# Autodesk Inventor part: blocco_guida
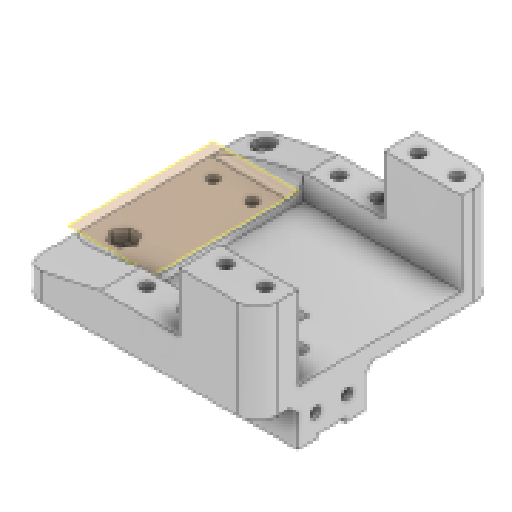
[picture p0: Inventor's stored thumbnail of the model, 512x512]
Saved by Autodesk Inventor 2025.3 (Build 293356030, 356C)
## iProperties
Created: 2026-02
Part Number: blocco_guida
Material: Plastica PET
Document SubType Name: Modeling
Designer: R5800u
Density: 1.541 g/cm^3
Appearance: Alluminio - Scuro
Author: R5800u
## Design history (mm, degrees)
sketch "Schizzo1"
  geometry: L1 (30, -3.5)-(-30, -3.5); L2 (-30, -3.5)-(-30, 3.5); L3 (-30, 3.5)-(30, 3.5); L4 (30, 3.5)-(30, -3.5); L5 (30, -3.5)-(-30, 3.5); L6 (-30, -3.5)-(30, 3.5); L7 (30, -3.5)-(-30, -3.5); L8 (-30, -3.5)-(-30, -8.5); L9 (-30, -8.5)-(30, -8.5); L10 (30, -8.5)-(30, -3.5); L11 (30, 3.5)-(-30, 3.5); L12 (-30, 3.5)-(-30, 8.5); L13 (-30, 8.5)-(30, 8.5); L14 (30, 8.5)-(30, 3.5); 3 further points
  constraints: 28 end point, 6 parallel, 3 horizontal, 3 perpendicular, 2 midpoint, 1 point on line
  dimensions: "d0" = 60 distance of L2.end L3.end; "d1" = 7 distance of L1.end L2.end; "d2" = 5 distance of L8.end L7.end; "d3" = 5 distance of L11.end L12.end
node "Piano di lavoro1"
extrude "Estrusione1" new body sketch "Schizzo1" stored distance "d4" = 10; taper "d5" = 0 deg
extrude "Estrusione2" cut sketch "Schizzo1" distance "d6" = 1; taper "d7" = 0 deg
sketch "Schizzo2"
  geometry: L1 (-30, 8.5)-(30, 8.5) reference; L2 (-16, -8.5)-(16, -8.5); L3 (16, -8.5)-(16, 8.5); L4 (16, 8.5)-(-16, 8.5); L5 (-16, 8.5)-(-16, -8.5); L6 (-16, -8.5)-(16, 8.5); L7 (16, -8.5)-(-16, 8.5); 2 further points
  constraints: 12 end point, 2 midpoint, 2 parallel, 1 horizontal, 1 perpendicular, 1 point on line
  dimensions: "d8" = 32 distance of L4.end L3.end
extrude "Estrusione3" cut sketch "Schizzo2" extent not by distance; stored distance "d9" = 0; taper "d10" = 0 deg
sketch "Schizzo3"
  geometry: L1 (-14, 14.1)-(-14, 0) reference; L2 (-14, 0)-(0, 0) reference; L3 (0, 0)-(0, 14.1) reference; L4 (-14, 14.1)-(0, 14.1) reference; L5 (-46, 0)-(-46, 14.1) reference; L6 (-60, 14.1)-(-46, 14.1) reference; L7 (-60, 0)-(-60, 14.1) reference; L8 (-60, 0)-(-46, 0) reference; L9 (0, 14.1)-(-60, 14.1); L10 (-60, 14.1)-(-60, 10.1); L11 (-60, 10.1)-(0, 10.1); L12 (0, 10.1)-(0, 14.1); 4 further points
  constraints: 8 end point, 2 parallel, 1 horizontal, 1 perpendicular, 1 point on line
  dimensions: "d11" = 4 distance of L10.end L9.end
extrude "Estrusione4" join sketch "Schizzo3" distance "d12" = 33; taper "d13" = 0 deg
node "Piano di lavoro2"
sketch "Schizzo4"
  geometry: L1 (0, 10.1)-(14, 10.1) reference; L2 (14, 0)-(14, 14.1) reference; L3 (0, 14.1)-(14, 14.1) reference; L4 (0, 0)-(0, 14.1) reference; L5 (0, 0)-(14, 0) reference; L6 (46, 10.1)-(60, 10.1) reference; L7 (46, 14.1)-(46, 0) reference; L8 (46, 0)-(60, 0) reference; L9 (60, 0)-(60, 14.1) reference; L10 (46, 14.1)-(60, 14.1) reference; L11 (0, 10.1)-(60, 10.1); L12 (60, 10.1)-(60, 14.1); L13 (60, 14.1)-(0, 14.1); L14 (0, 14.1)-(0, 10.1); 7 further points
  constraints: 8 end point, 2 parallel, 1 horizontal, 1 perpendicular
extrude "Estrusione5" join sketch "Schizzo4" stored distance "d14" = 7; taper "d15" = 0 deg
sketch "Schizzo5"
  geometry: L1 (60, -60.375)-(60, 0) reference; L2 (0, 0)-(60, 0) reference; L3 (0, 0)-(0, -60.375) reference; L4 (0, -60.375)-(60, -60.375) reference; L5 (46, -50)-(14, -50) reference; L6 (14, -50)-(14, -33) reference; L7 (14, -33)-(46, -33) reference; L8 (46, -33)-(46, -50) reference; L9 (60, -33)-(60, 0) reference; L10 (60, 0)-(40.3, 0); L11 (40.3, 0)-(40.3, -8.3); L12 (40.3, -8.3)-(60, -8.3); L13 (60, -8.3)-(60, 0); C1 r 1.5 at (45.2, -4.5); C2 r 1.5 at (55.2, -4.5); A1 r 2.122 centre (45.2, -4.5) between (43.95, -2.785) and (46.45, -2.785) reference; A2 r 2.114 centre (55.2, -4.5) between (53.95, -2.795) and (56.45, -2.795) reference; 3 further points
  constraints: 8 end point, 4 centre point, 4 point on circle, 2 coincident, 2 parallel, 1 horizontal, 1 perpendicular, 8 other
  dimensions: "d16" = 19.7 distance of L12.end L11.end; "d17" = 8.3 distance of L11.end L10.end; "d18" = 3 diameter of C1; "d19" = 3 diameter of C2
  node "Linea chiusa proiettata5"
node "Piano di lavoro3"
extrude "Estrusione6" join sketch "Schizzo5" stored distance "d20" = 10; taper "d21" = 0 deg
sketch "Schizzo6"
  geometry: L1 (40.3, 52.075)-(40.3, 60.375) reference; L2 (0, 60.375)-(40.3, 60.375) reference; L3 (0, 60.375)-(0, 0) reference; L4 (0, 0)-(60, 0) reference; L5 (60, 0)-(60, 52.075) reference; L6 (60, 52.075)-(40.3, 52.075) reference; L7 (46, 10.375)-(14, 10.375) reference; L8 (14, 10.375)-(14, 27.375) reference; L9 (14, 27.375)-(46, 27.375) reference; L10 (46, 27.375)-(46, 10.375) reference; L11 (60, 60.375)-(40.3, 60.375) reference; L12 (40.3, 60.375)-(20.3, 60.375); L13 (20.3, 60.375)-(20.3, 52.075); L14 (20.3, 52.075)-(40.3, 52.075); L15 (40.3, 52.075)-(40.3, 60.375); C1 r 1.5 at (25, 55.875); C2 r 1.5 at (35, 55.875); A1 r 2.122 centre (25, 55.875) between (23.75, 57.59) and (26.25, 57.59) reference; A2 r 2.114 centre (35, 55.875) between (33.75, 57.58) and (36.25, 57.58) reference; 4 further points
  constraints: 8 end point, 2 centre point, 2 coincident, 2 parallel, 1 horizontal, 1 perpendicular
  dimensions: "d22" = 20 distance of L1.start L13.end; "d24" = 3 diameter of C1; "d25" = 3 diameter of C2
  node "Linea chiusa proiettata6"
  node "Riferimento3"
  node "Riferimento4"
node "Piano di lavoro4"
extrude "Estrusione7" join sketch "Schizzo6" stored distance "d26" = 10; taper "d27" = 0 deg
sketch "Schizzo7"
  geometry: L1 (20.3, 51.875)-(20.3, 60.375) reference; L2 (0, 60.375)-(20.3, 60.375) reference; L3 (0, 60.375)-(0, 0) reference; L4 (0, 0)-(60, 0) reference; L5 (60, 0)-(60, 51.875) reference; L6 (60, 51.875)-(20.3, 51.875) reference; L7 (47, 10.375)-(13, 10.375) reference; L8 (13, 10.375)-(13, 27.375) reference; L9 (13, 27.375)-(47, 27.375) reference; L10 (47, 27.375)-(47, 10.375) reference; L11 (0, 0)-(60, 0) reference; L12 (60, 0)-(40.1, 0); L13 (40.1, 0)-(40.1, 10.375); L14 (40.1, 10.375)-(60, 10.375); L15 (60, 10.375)-(60, 0); C1 r 1.5 at (45.2, 6.875); C2 r 1.5 at (55.2, 6.875); A1 r 2.534 centre (45.2, 6.875) between (46.45, 4.67) and (43.95, 4.67); A2 r 2.122 centre (55.2, 6.875) between (56.45, 5.16) and (53.95, 5.16); A3 r 2.122 centre (45.2, 6.875) between (46.45, 5.16) and (43.95, 5.16) reference; A4 r 2.114 centre (55.2, 6.875) between (56.45, 5.17) and (53.95, 5.17) reference; 3 further points
  constraints: 8 end point, 8 point on circle, 6 centre point, 4 coincident, 2 parallel, 1 horizontal, 1 perpendicular, 1 point on line, 8 other
  dimensions: "d28" = 19.9 distance of L13.end L14.end; "d30" = 3 diameter of C1; "d31" = 3 diameter of C2
  node "Linea chiusa proiettata7"
node "Piano di lavoro5"
extrude "Estrusione8" join sketch "Schizzo7" stored distance "d32" = 10; taper "d33" = 0 deg
sketch "Schizzo8"
  geometry: L1 (40.1, 10.3)-(60, 10.3) reference; L2 (60, 10.3)-(60, 51.875) reference; L3 (60, 51.875)-(20.3, 51.875) reference; L4 (20.3, 51.875)-(20.3, 60.375) reference; L5 (0, 60.375)-(20.3, 60.375) reference; L6 (0, 60.375)-(0, 0) reference; L7 (0, 0)-(40.1, 0) reference; L8 (40.1, 0)-(40.1, 10.3) reference; L9 (47, 10.375)-(13, 10.375) reference; L10 (13, 10.375)-(13, 27.375) reference; L11 (13, 27.375)-(47, 27.375) reference; L12 (47, 27.375)-(47, 10.375) reference; L13 (40.1, 0)-(19.9, 0); L14 (19.9, 0)-(19.9, 10.5); L15 (19.9, 10.5)-(40.1, 10.5); L16 (40.1, 10.5)-(40.1, 0); C1 r 1.5 at (25, 6.875); C2 r 1.5 at (35, 6.875); A1 r 2.122 centre (25, 6.875) between (26.25, 5.16) and (23.75, 5.16) reference; A2 r 2.114 centre (35, 6.875) between (36.25, 5.17) and (33.75, 5.17) reference; 7 further points
  constraints: 8 end point, 2 centre point, 2 coincident, 2 parallel, 1 horizontal, 1 perpendicular
  dimensions: "d34" = 20.2 distance of L14.end L15.end; "d35" = 10.5 distance of L13.end L14.end; "d36" = 3 diameter of C1; "d37" = 3 diameter of C2
  node "Linea chiusa proiettata8"
  node "Riferimento7"
  node "Riferimento8"
node "Piano di lavoro6"
extrude "Estrusione9" join sketch "Schizzo8" stored distance "d38" = 10; taper "d39" = 0 deg
sketch "Schizzo9"
  geometry: C1 r 10.5 at (16, 8.5); 1 further point
  constraints: 1 centre point, 1 coincident
  dimensions: "d40" = 21 diameter of C1
extrude "Estrusione10" cut sketch "Schizzo9" stored distance "d41" = 3; taper "d42" = 0 deg
sketch "Schizzo12"
  geometry: C1 r 1.5 at (45.2, 3.5) reference; C2 r 1.5 at (55.2, 3.5) reference; C3 r 1.5 at (35, 3.5) reference; C4 r 1.5 at (25, 3.5) reference; C5 r 1.5 at (25, -45.5) reference; C6 r 1.5 at (35, -45.5) reference; C7 r 1.5 at (45.2, -45.5) reference; C8 r 1.5 at (55.2, -45.5) reference; 2 further points
  constraints: 1 other
hole "Foro1" sketch "Schizzo12" at (35, 3.5), (55.2, 3.5), (25, 3.5), (25, -45.5), (35, -45.5), (45.2, -45.5), (55.2, -45.5), (45.2, 3.5) diameter "d53" = 3.2; stored, may be unused: countersink angle "d57" = 90 deg, drill point angle "d59" = 118 deg; dims "d54" = 6, "d55" = 5.6, "d56" = 3, "d58" = 8
sketch "Schizzo13"
  geometry: L1 (0, 0)-(0, 4) reference; L2 (60, 0)-(0, 0) reference; L3 (60, 0)-(60, 25.2) reference; L4 (40.1, 25.2)-(60, 25.2) reference; L5 (40.1, 10.2)-(40.1, 25.2) reference; L6 (19.9, 10.2)-(40.1, 10.2) reference; L7 (19.9, 4)-(19.9, 10.2) reference; L8 (0, 4)-(19.9, 4) reference; L9 (0, 4)-(19.9, 4) reference; L10 (0, 4)-(0, 6); L11 (0, 6)-(19.9, 10.2); 1 further point
  constraints: 4 end point, 1 vertical
  dimensions: "d60" = 2 distance of L1.end L10.end
extrude "Estrusione13" join sketch "Schizzo13" stored distance "d61" = 10; taper "d62" = 0 deg
sketch "Schizzo14"
  geometry: L1 (0, 10.1)-(0, 14.1) reference; L2 (0, 14.1)-(-20.3, 14.1) reference; L3 (-20.3, 14.1)-(-20.3, 20.3) reference; L4 (-40.3, 20.3)-(-20.3, 20.3) reference; L5 (-40.3, 20.3)-(-40.3, 35.3) reference; L6 (-60, 35.3)-(-40.3, 35.3) reference; L7 (-60, 10.1)-(-60, 35.3) reference; L8 (-60, 10.1)-(0, 10.1) reference; L9 (0, 10.1)-(0, 16.1) reference; L10 (0, 14.1)-(0, 16.1); L11 (0, 16.1)-(-20.3, 20.3); 1 further point
  constraints: 4 end point, 1 collinear
extrude "Estrusione14" join sketch "Schizzo14" stored distance "d63" = 10; taper "d64" = 0 deg
sketch "Schizzo15"
  geometry: C1 r 2.8 at (9.036, -28.5) reference; C2 r 2.8 at (19.036, -28.5) reference; C3 r 2.8 at (9.036, 20.5) reference; A1 r 2.8 centre (19.036, 20.5) between (21.836, 20.5) and (21.836, 20.5) reference; 5 further points
  constraints: 4 coincident
hole "Foro2" sketch "Schizzo15" at (9.036, -28.5), (19.036, -28.5), (19.036, 20.5), (9.036, 20.5) diameter "d68" = 3.2; stored, may be unused: countersink angle "d72" = 90 deg, drill point angle "d74" = 118 deg; dims "d69" = 6, "d70" = 5.6, "d71" = 6, "d73" = 8
sketch "Schizzo16"
  geometry: L1 (27.375, 16.1)-(17, 16.1) reference; L2 (17, 14.1)-(17, 16.1) reference; L3 (-24.7, 14.1)-(17, 14.1) reference; L4 (-24.7, 14.1)-(-24.7, 16.1) reference; L5 (-33, 16.1)-(-24.7, 16.1) reference; L6 (0, 10.1)-(-33, 10.1) reference; L7 (0, 0)-(0, 10.1) reference; L8 (0, 0)-(5, 0) reference; L9 (5, 0)-(5, 1) reference; L10 (5, 1)-(12, 1) reference; L11 (12, 1)-(12, 0) reference; L12 (12, 0)-(17, 0) reference; L13 (17, 0)-(17, 10.1) reference; L14 (17, 10.1)-(27.375, 10.1) reference; L15 (-24.7, 16.1)-(-24.7, 20.3) reference; L16 (-24.7, 16.1)-(17, 16.1); L17 (27.375, 10.1)-(27.375, 16.1) reference; L18 (-33, 10.1)-(-33, 16.1) reference; 1 further point
  constraints: 2 end point, 1 perpendicular
extrude "Estrusione15" join sketch "Schizzo16" distance "d75" = 19.8; taper "d76" = 0 deg
fillet "Raccordo6" dims "d77" = 4
chamfer "Smusso2" distance "d78" = 2; stored, may be unused: second distance "d79" = 2, angle "d80" = 45 deg
sketch "Schizzo17"
  geometry: L1 (0, 1)-(-7, 1) reference; L2 (-3.5, 1)-(-3.5, 6); L3 (-3.5, 6)-(0.5, 6); L4 (-3.5, 6)-(-7.5, 6); 1 further point
  constraints: 6 end point, 1 horizontal, 1 midpoint, 1 perpendicular, 1 vertical
  dimensions: "d81" = 5 distance of L2.start L2.end; "d82" = 4 distance of L2.end L3.end; "d83" = 4 distance of L2.end L4.end
hole "Foro3" sketch "Schizzo17" at (0.5, 6), (-7.5, 6) diameter "d84" = 2.7; stored, may be unused: countersink angle "d88" = 90 deg, drill point angle "d90" = 118 deg; dims "d85" = 6, "d86" = 6.5, "d87" = 3.4, "d89" = 8
mirror "Speculare1"
fillet "Raccordo7" dims "d91" = 5
sketch "Schizzo18"
  geometry: C1 r 1.2 at (-22.885, 0) reference; C2 r 1.2 at (22.115, 0) reference; 1 further point
hole "Foro4" sketch "Schizzo18" at (22.115, 0), (-22.885, 0) diameter "d92" = 3.2; stored, may be unused: countersink angle "d96" = 90 deg, drill point angle "d98" = 118 deg; dims "d93" = 6, "d94" = 4, "d95" = 2, "d97" = 8
sketch "Schizzo19" dims "d99" = 6.6
  geometry: L1 (3.815, 4.5)-(5.465, 7.358); L2 (5.465, 7.358)-(8.765, 7.358); L3 (8.765, 7.358)-(10.415, 4.5); L4 (10.415, 4.5)-(8.765, 1.642); L5 (8.765, 1.642)-(5.465, 1.642); L6 (5.465, 1.642)-(3.815, 4.5); C1 r 1.6 at (7.115, 4.5) reference; 3 further points
  constraints: 12 end point, 2 coincident, 1 horizontal alignment, 15 other
extrude "Estrusione16" cut sketch "Schizzo19" distance "d100" = 3; taper "d101" = 0 deg
sketch "Schizzo20"
  geometry: L1 (-36.164, -2)-(-36.164, -28) reference; L2 (18.836, -33)-(-31.164, -33) reference; L3 (-20.664, -15.875)-(-30.664, -15.875); L4 (-30.664, -15.875)-(-30.664, -28.875); C1 r 1.5 at (-20.664, -15.875) reference; 1 further point
  constraints: 4 end point, 1 horizontal, 1 perpendicular
  dimensions: "d114" = 10 distance of L3.start L3.end; "d116" = 13 distance of L3.end L4.end
hole "Foro5" sketch "Schizzo20" at (-20.664, -15.875), (-30.664, -15.875), (-30.664, -28.875) diameter "d104" = 2.7; stored, may be unused: countersink angle "d108" = 90 deg, drill point angle "d110" = 118 deg; dims "d105" = 6, "d106" = 5.5, "d107" = 2.9, "d109" = 8
node "Piano di lavoro7"
sketch "Schizzo21"
  geometry: C1 r 1.35 at (5.5, 41.875) reference; 1 further point
hole "Foro6" sketch "Schizzo21" at (5.5, 41.875) diameter "d118" = 2.7; stored, may be unused: countersink angle "d122" = 90 deg, drill point angle "d124" = 118 deg; dims "d119" = 6, "d120" = 5, "d121" = 2.9, "d123" = 8
node "Solido1"
node "Linea chiusa proiettata1"
node "Linea chiusa proiettata2"
node "Linea chiusa proiettata3"
node "Linea chiusa proiettata4"
node "Linea chiusa proiettata10"
node "Linea chiusa proiettata11"
node "Linea chiusa proiettata12"
node "Linea chiusa proiettata13"
node "Riferimento9"
node "Riferimento10"
node "Riferimento11"
other parameters: "d117" = 1.75
